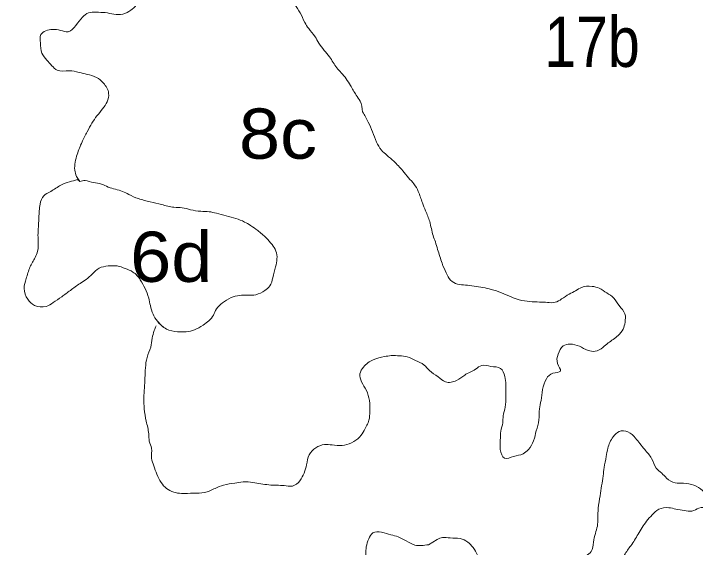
# Model space of a CAD drawing. Extents: x 854879 to 917879, y 8541948 to 8631048.
# Drawn here: x 876112 to 881265, y 8600736 to 8604775 of the extents above; entities that cross this region are included whole.
import ezdxf
from ezdxf.enums import TextEntityAlignment as Align

# ---------------------------------------------------------------- set-up
doc = ezdxf.new("R2010")
doc.units = 0
doc.header["$LTSCALE"] = 150
for name, color, linetype, lineweight in [('1', 7, 'Continuous', 13), ('12', 7, 'Continuous', 13), ('30', 7, 'Continuous', 13), ('35', 7, 'Continuous', 13)]:
    doc.layers.add(name, color=color, linetype=linetype, lineweight=lineweight)

msp = doc.modelspace()

# ---------------------------------------------------------------- linework, layer by layer
at = {"layer": '12'}
msp.add_spline([(871540.4, 8601616.3), (871630.5, 8601735.3), (871725.4, 8601821.2), (871819.8, 8601853.5), (871913.6, 8601811.8), (872009.1, 8601696.2), (872090.3, 8601675.1), (872352.9, 8601741.6), (872559.5, 8601800.9), (872768.1, 8601811.8), (872925.4, 8601774.7), (873100.7, 8601750.2), (873246.8, 8601606.1), (873273.5, 8601468.2), (873319, 8601169.5), (873340.7, 8601036.7), (873373.3, 8600995.6), (873443.9, 8600926.1), (873503.6, 8600780.3), (873522.1, 8600586.3), (873508.5, 8600492.1), (873474.4, 8600380.2), (873420, 8600283.8), (873381.1, 8600200.1), (873357.3, 8600100.8), (873362, 8600065.1), (873409.5, 8599978), (873462.5, 8599931.6), (873479.8, 8599877.9), (873496.2, 8599735), (873544.2, 8599691.2), (873656.2, 8599700.4), (873722.2, 8599694.7), (873826.1, 8599653), (873995.5, 8599546.9), (874109.6, 8599510.2), (874211.1, 8599483.8), (874337.8, 8599434.2), (874512.3, 8599325.6), (874651.2, 8599230), (875018.4, 8599061), (875087.1, 8599057.8), (875338.8, 8599055.6), (875519.1, 8599020.8), (875668.6, 8598958.3), (875830.2, 8598834.4), (875958.9, 8598728.8), (876150.9, 8598599.6), (876310.4, 8598521.6), (876408.6, 8598411.1), (876455.5, 8598257.7), (876426.2, 8598117.8), (876378.7, 8597942.2), (876270.1, 8597752), (876109.2, 8597679.5), (875976.3, 8597614.4), (875804.4, 8597452.8), (875707.7, 8597173.2), (875751.7, 8596986.7), (875975.9, 8596760.3), (876322.9, 8596879.6), (876473.4, 8596924.1), (876641.3, 8596925.2), (876864.4, 8596851.8), (877033.9, 8596758.4), (877155.5, 8596706.4), (877330.8, 8596681.8), (877637.5, 8596574.6), (877735.6, 8596464.1), (877833.9, 8596368.8), (877847.3, 8596172.4), (877866.3, 8596032), (877934, 8595926.8), (877996.9, 8595847.2), (878121.1, 8595810.4), (878200.3, 8595840.3), (878305.4, 8595933.7), (878443.6, 8596021.7), (878604, 8596043.2), (878718.1, 8596009.1), (878788.7, 8595934.5), (878909.3, 8595783), (878997.5, 8595698), (879448.4, 8595500.2), (879534.2, 8595435.7), (879780.2, 8595089.3), (879859.7, 8594887.2), (879937.8, 8594544.8), (880031, 8594442), (880132.2, 8594385), (880269.2, 8594358.3)], degree=3, dxfattribs=at)
at = {"layer": '30'}
for p, q in [((876612.8, 8603505.7), (876587.2, 8603542.8)), ((879312.7, 8600796.3), (879247.4, 8600755.9))]:
    msp.add_line(p, q, dxfattribs=at)
for points in [[(876587.2, 8603542.8), (876574.1, 8603591.3), (876577.3, 8603650.9), (876592.3, 8603709.8), (876628.8, 8603803.6), (876668.5, 8603881.2), (876703.6, 8603947.1), (876741.9, 8604000.8), (876784.2, 8604054.4), (876818.7, 8604108.4), (876829.9, 8604171.5), (876790.8, 8604249.2), (876737.9, 8604291.8), (876668.2, 8604315.3), (876606, 8604330.5), (876531.7, 8604342.3), (876441.3, 8604347), (876399.8, 8604381.1), (876362.6, 8604422.8), (876326.1, 8604476.5), (876314.4, 8604552.8), (876317.9, 8604616.3), (876406.7, 8604655.5), (876465.4, 8604648.5), (876524, 8604637.5), (876581.8, 8604686.3), (876632.3, 8604747.4), (876677.5, 8604780.9), (876736.9, 8604785.8), (876803.7, 8604782.3), (876870.1, 8604770.9), (876937.1, 8604771.4), (876997.8, 8604800.1), (877039.2, 8604837.8), (877093.5, 8604894.7), (877127.8, 8604944.7), (877139.2, 8605011.8), (877147, 8605083.1), (877130, 8605131.8), (877093.6, 8605189.5), (877054.5, 8605267.2), (877014, 8605321.1), (876973.1, 8605367), (876932.7, 8605420.9), (876911.7, 8605469.8), (876900, 8605546.1), (876903.2, 8605605.6), (876930.4, 8605671.9), (876985.4, 8605740.8), (877042.7, 8605781.6), (877095.6, 8605810.7), (877147.9, 8605831.9), (877204.2, 8605852.9), (877267.6, 8605857.6), (877326.5, 8605854.5), (877406, 8605866.3), (877465.1, 8605867.2), (877524.3, 8605868.1), (877602.5, 8605856.1), (877656.7, 8605837.4), (877698.4, 8605807.3), (877758.9, 8605760.3), (877815.5, 8605713.6), (877844.6, 8605668.3), (877895.8, 8605593.9), (877948.1, 8605539.4), (877995.3, 8605465.3), (878030.8, 8605391.7), (878063.6, 8605342.2), (878088.5, 8605293.1), (878124.4, 8605227.6), (878149.3, 8605178.4), (878146.3, 8605122.8), (878162.4, 8605054.3), (878175.1, 8604997.9), (878192, 8604945.2), (878209.1, 8604896.5), (878237.7, 8604843.3), (878277.7, 8604781.4), (878313.2, 8604707.9), (878342.3, 8604662.6), (878390.2, 8604600.3), (878419.1, 8604551), (878459.5, 8604497.2), (878500.2, 8604447.2), (878554.9, 8604364.7), (878588.3, 8604327.2), (878658.1, 8604231.9), (878701.4, 8604158), (878730.5, 8604112.7), (878749.8, 8604032)], [(878749.8, 8604032), (878792.9, 8603954.1), (878824.4, 8603880.7), (878855.7, 8603803.4), (878891.8, 8603741.8), (878933.1, 8603703.8), (878985.8, 8603657.3), (879052.9, 8603586.1), (879097.3, 8603532), (879138.2, 8603486), (879170.6, 8603428.6), (879201.5, 8603343.3), (879225.8, 8603282.3), (879256.9, 8603201.1), (879282.7, 8603096.2), (879299.8, 8603047.5), (879316.5, 8602990.8), (879333.4, 8602938.2), (879350.2, 8602885.5), (879381.8, 8602812.2), (879414.3, 8602758.7), (879467.9, 8602728.1), (879526.6, 8602721), (879593.2, 8602713.6), (879659.6, 8602702.2), (879721.9, 8602687), (879799.4, 8602663), (879872.6, 8602631.4), (879934.4, 8602608.2), (880012.6, 8602596.2), (880087.3, 8602592.3), (880146.2, 8602589.3), (880205.4, 8602590.2), (880254.1, 8602615.5), (880311.2, 8602652.4), (880359.9, 8602677.8), (880404.6, 8602703.3), (880483.9, 8602711.1), (880538.2, 8602696.4), (880595.5, 8602661.5), (880648.6, 8602622.9), (880688.8, 8602565.1), (880732.8, 8602503), (880733.3, 8602439.3), (880718.7, 8602388.3), (880680.6, 8602338.5), (880606.6, 8602282.6), (880565.4, 8602248.8), (880508.7, 8602219.9), (880453.8, 8602226.8), (880388.5, 8602258), (880318.4, 8602273.6), (880266.5, 8602260.4), (880227.7, 8602198.7), (880223.8, 8602127.2), (880244.4, 8602070.3), (880188.3, 8602053.3), (880138.8, 8602012.1), (880110.7, 8601929.9), (880098.4, 8601846.9), (880087.1, 8601783.8), (880082.6, 8601700.3), (880062.4, 8601617.7), (880042.6, 8601543.1), (880003.6, 8601477.4), (879962.4, 8601443.7), (879890.3, 8601423.5), (879822.7, 8601411.1), (879790.7, 8601476.5), (879790.6, 8601548.2), (879794.3, 8601615.7), (879809.5, 8601678.7), (879812.3, 8601730.3), (879827.7, 8601797.2), (879832, 8601876.7), (879833, 8601968.2), (879824.4, 8602028.4), (879792.2, 8602089.8), (879718.2, 8602105.6), (879651.6, 8602113.1), (879602.7, 8602083.8), (879521.5, 8602040.2), (879460.2, 8601999.5), (879376.8, 8601987.9), (879319.8, 8602026.7), (879255.3, 8602073.9), (879214.2, 8602115.9), (879149.1, 8602151.1), (879087.5, 8602178.2), (879028.8, 8602185.2), (878965.9, 8602188.5)], [(877200.6, 8602444.6), (877266.1, 8602388.3), (877351.7, 8602367.9), (877478.5, 8602381.2), (877543.5, 8602417.7), (877622.5, 8602493.3), (877644.7, 8602539.9), (877690.5, 8602585.3), (877755.7, 8602625.8), (877819.7, 8602642.4), (877878.9, 8602643.3), (877942.2, 8602647.9), (878010.9, 8602680.2), (878048.2, 8602714.1), (878071.3, 8602776.7), (878091.5, 8602859.3), (878102.6, 8602918.4), (878094, 8602978.6), (878065.1, 8603027.9), (878020.5, 8603078.1), (877956.5, 8603133.2), (877903.4, 8603171.8), (877857.5, 8603198), (877792, 8603225.3), (877718.1, 8603245.1), (877644.3, 8603264.9), (877589.7, 8603275.7), (877526.8, 8603278.9), (877448.6, 8603291), (877386.4, 8603306.2), (877323.5, 8603309.4), (877230, 8603330.2), (877144.4, 8603350.6), (877055.1, 8603375.1), (876981.9, 8603406.8), (876935.8, 8603429.1), (876827.3, 8603462.6), (876777.2, 8603485.2), (876714.8, 8603496.4), (876652.5, 8603511.6), (876612.8, 8603505.7)], [(878965.9, 8602188.5), (878914.1, 8602179.2), (878830.1, 8602155.7), (878756.1, 8602099.8), (878729.8, 8602049.4), (878742.3, 8601989), (878778.2, 8601923.4), (878801.6, 8601846.5), (878805, 8601762.7), (878797.7, 8601699.3), (878761.9, 8601621.5), (878727.7, 8601571.5), (878666.2, 8601526.9), (878594.2, 8601506.8), (878519.5, 8601510.7), (878460.5, 8601513.7), (878396.1, 8601489.2), (878346, 8601436), (878326.2, 8601361.4), (878307.1, 8601298.6), (878276.3, 8601240.5), (878219, 8601199.6), (878156.1, 8601202.9), (878101, 8601205.8), (878042.1, 8601208.8), (877920.9, 8601227.1), (877846.2, 8601230.9), (877782.7, 8601222.3), (877699.1, 8601206.7), (877634.7, 8601182.2), (877554.2, 8601150.5), (877471.2, 8601146.8), (877380.3, 8601143.6), (877321.8, 8601154.6), (877268.1, 8601181.3), (877227.2, 8601227.2), (877195, 8601288.7), (877170.9, 8601353.6), (877154.3, 8601410.3), (877154.4, 8601485.9), (877137.5, 8601538.6), (877132.7, 8601594.6), (877114.2, 8601691.2), (877099.5, 8601783.6), (877096.1, 8601867.4), (877100.2, 8601942.8), (877104.2, 8602018.3), (877108.3, 8602093.8), (877120.4, 8602172.8), (877148.3, 8602251), (877159.8, 8602318.1), (877174.8, 8602377.1), (877188.5, 8602412.2)], [(881383.7, 8600975.6), (881358.9, 8601028.6), (881292.1, 8601032.1), (881239.7, 8601010.9), (881180.8, 8601014), (881118.3, 8601025.2), (881063.7, 8601036), (880988.2, 8601024), (880938.7, 8600982.7), (880896.6, 8600933.1), (880832.3, 8600836.9), (880806.1, 8600790.5), (880776.3, 8600748.2), (880729.2, 8600678.9), (880698.7, 8600624.8), (880651.6, 8600555.5), (880609.1, 8600498), (880541.9, 8600421.8), (880491.8, 8600368.6), (880441, 8600303.6), (880404.8, 8600217.8), (880405.3, 8600154.1), (880413.3, 8600081.9), (880410.3, 8600026.3), (880402.9, 8599963), (880370.7, 8599877), (880340, 8599818.9), (880288.6, 8599741.9), (880236.6, 8599728.6), (880178.7, 8599751.6), (880149.8, 8599800.9), (880130.1, 8599873.6), (880134, 8599945.1), (880153.1, 8600007.8), (880164.8, 8600078.9), (880168.4, 8600146.4), (880139.3, 8600191.8), (880087.5, 8600254.2), (880058.2, 8600295.6), (880041.3, 8600348.2), (880044.6, 8600407.8), (880067.4, 8600466.3), (880097.5, 8600512.6), (880143.5, 8600562), (880200.2, 8600590.9), (880268.3, 8600611.3), (880327.7, 8600616.1), (880399.1, 8600624.4), (880441, 8600670), (880478.3, 8600703.9), (880493.9, 8600774.8), (880509.3, 8600841.7), (880524.1, 8600896.7), (880527.3, 8600956.3), (880531.4, 8601031.8), (880544.4, 8601126.7), (880556.3, 8601201.7), (880568.2, 8601276.8), (880575.6, 8601340.2), (880591.9, 8601423), (880603.2, 8601486.1), (880643.2, 8601571.7), (880688.8, 8601613.1), (880755.6, 8601609.6), (880812.2, 8601562.9), (880845.5, 8601521.3), (880882.4, 8601475.6), (880934, 8601409.2), (880969.5, 8601335.6), (881010.8, 8601297.6), (881048.2, 8601259.8), (881113.3, 8601224.6), (881176.2, 8601221.3), (881254.2, 8601205.3), (881319, 8601166.1), (881356.6, 8601132.3), (881423.5, 8601128.8), (881487.2, 8601141.5), (881521.2, 8601187.5), (881528.6, 8601250.8), (881528, 8601314.6), (881511.4, 8601371.2), (881515.7, 8601450.7), (881530.9, 8601513.6), (881542.6, 8601584.7), (881565.9, 8601651.2), (881578, 8601730.2), (881617, 8601795.9), (881663.5, 8601853.3), (881700.8, 8601887.2), (881750.1, 8601924.4)], [(879247.4, 8600755.9), (879144.8, 8600753.2), (879079.5, 8600784.5), (879018.1, 8600815.6), (878963.7, 8600830.4), (878893.8, 8600849.9), (878826.6, 8600845.4), (878796.5, 8600799.2), (878777.6, 8600740.4), (878774.6, 8600684.8), (878770.7, 8600613.3), (878767.9, 8600561.7), (878732.7, 8600491.8), (878690.3, 8600438.3), (878634.5, 8600425.2), (878575.5, 8600428.3), (878529.9, 8600386.9), (878499.8, 8600340.6), (878477.6, 8600294), (878458.1, 8600223.3), (878463.1, 8600171.2), (878456, 8600111.9), (878429.2, 8600053.5), (878418.1, 8599994.3), (878422.2, 8599922.4), (878451.5, 8599881.1), (878510, 8599870.1), (878576.8, 8599866.6), (878649.3, 8599894.7), (878720.9, 8599906.9), (878783.8, 8599903.7), (878884.5, 8599870.6), (878953.7, 8599839.1), (879003.3, 8599808.6), (879073.4, 8599793), (879132.6, 8599793.9), (879202, 8599838.1), (879248.8, 8599903.4), (879286.6, 8599945.3), (879335.6, 8599978.6), (879399.2, 8599987.2), (879480.9, 8599967), (879547, 8599951.7), (879603.6, 8599976.6), (879645.6, 8600026.2), (879672.4, 8600084.6), (879675.4, 8600140.2), (879650.7, 8600193.2), (879611.1, 8600263), (879602.1, 8600315.2), (879606.1, 8600390.7), (879616.8, 8600441.9), (879627.6, 8600497.2), (879630.6, 8600552.8), (879634.3, 8600620.3), (879617.6, 8600676.9), (879585.2, 8600734.4), (879544.1, 8600776.3), (879486.5, 8600803.2), (879411.8, 8600807.1), (879352.8, 8600810.2), (879312.7, 8600796.3)]]:
    msp.add_spline(points, degree=3, dxfattribs=at)
at = {"layer": '35'}
msp.add_line((876612.8, 8603505.7), (876593.8, 8603518.6), dxfattribs=at)
msp.add_spline([(876593.8, 8603518.6), (876533.8, 8603501.8), (876469.4, 8603477.2), (876391.9, 8603429.5), (876338.9, 8603396.4), (876311.9, 8603334.1), (876302.4, 8603231), (876299.6, 8603179.4), (876296, 8603111.8), (876296.9, 8603056), (876292.7, 8602976.6), (876274.4, 8602929.7), (876234.9, 8602856.1), (876206.6, 8602769.9), (876190.8, 8602695.1), (876218, 8602614), (876270.6, 8602567.4), (876356.9, 8602559), (876409.7, 8602588.1), (876475.1, 8602632.5), (876540.8, 8602680.9), (876614.6, 8602732.8), (876659.5, 8602762.3), (876705.1, 8602803.8), (876758.7, 8602848.8), (876826.6, 8602865.2), (876893.7, 8602865.7), (876955.7, 8602846.6), (877013.4, 8602819.7), (877069.3, 8602761), (877105.2, 8602695.4), (877132.8, 8602622.3), (877145.5, 8602565.8), (877165.7, 8602501.1), (877198.3, 8602447.6), (877266.1, 8602388.3), (877351.7, 8602367.9), (877478.5, 8602381.2), (877543.5, 8602417.7), (877622.5, 8602493.3), (877644.7, 8602539.9), (877690.5, 8602585.3), (877755.7, 8602625.8), (877819.7, 8602642.4), (877878.9, 8602643.3), (877942.2, 8602647.9), (878010.9, 8602680.2), (878048.2, 8602714.1), (878071.3, 8602776.7), (878091.5, 8602859.3), (878102.6, 8602918.4), (878094, 8602978.6), (878065.1, 8603027.9), (878020.5, 8603078.1), (877956.5, 8603133.2), (877903.4, 8603171.8), (877857.5, 8603198), (877792, 8603225.3), (877718.1, 8603245.1), (877644.3, 8603264.9), (877589.7, 8603275.7), (877526.8, 8603278.9), (877448.6, 8603291), (877386.4, 8603306.2), (877323.5, 8603309.4), (877230, 8603330.2), (877144.4, 8603350.6), (877055.1, 8603375.1), (876981.9, 8603406.8), (876935.8, 8603429.1), (876827.3, 8603462.6), (876777.2, 8603485.2), (876714.8, 8603496.4), (876652.5, 8603511.6), (876612.8, 8603505.7)], degree=3, dxfattribs=at)

# ---------------------------------------------------------------- texts
at = {"layer": '1'}
for s, width, p in [('17b', 0.85, (880484.4, 8604371.9)), ('8c', 1.1, (878110.2, 8603677)), ('6d', 1.1, (877303.4, 8602745.1))]:
    msp.add_text(s, height=380, dxfattribs=dict(at, width=width)).set_placement(p, align=Align.CENTER)

doc.saveas('drawing.dxf')
